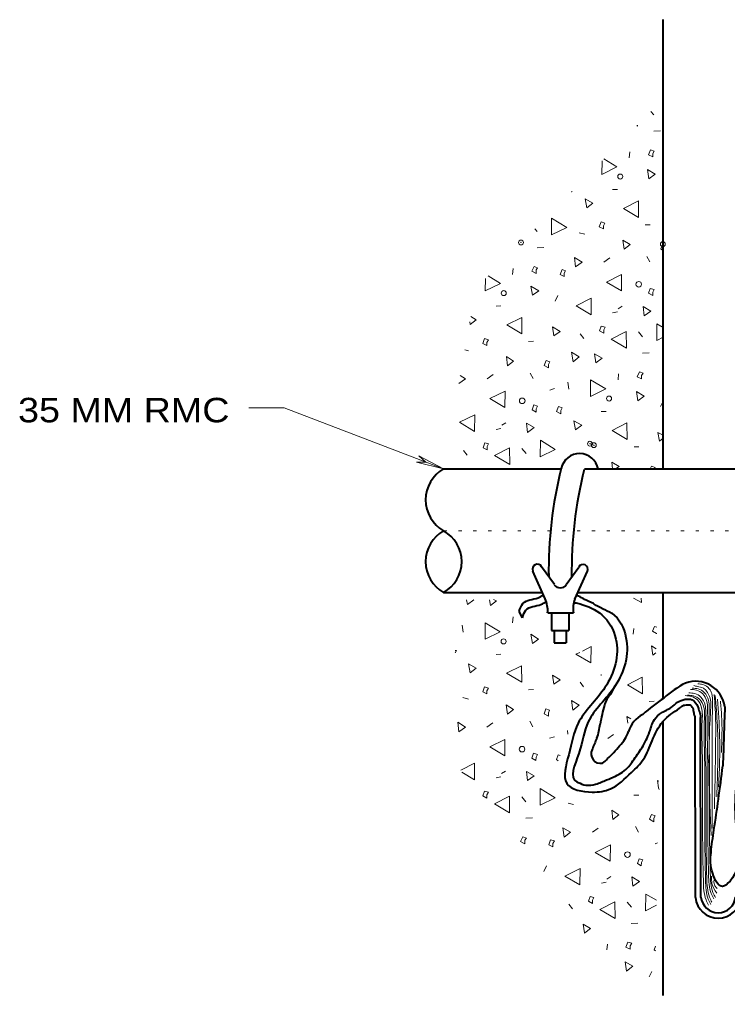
# Model space of a CAD drawing. Extents: x 312583 to 312854, y 144419 to 144597.
# Drawn here: x 312698.18 to 312720.15, y 144540.3 to 144570.57 of the extents above; entities that cross this region are included whole.
import ezdxf

# ---------------------------------------------------------------- set-up
doc = ezdxf.new("R2010")
doc.units = 0
doc.header["$LTSCALE"] = 0.3
doc.header["$PDMODE"] = 32
doc.header["$PDSIZE"] = 0.15
doc.linetypes.add('DOTTED', pattern=[1.5, 0.3, -1.2])
doc.layers.add('1', color=7, linetype='Continuous', lineweight=40)
doc.layers.add('2', color=7, linetype='Continuous', lineweight=13)

msp = doc.modelspace()

# ---------------------------------------------------------------- linework, layer by layer
at = {"layer": '1'}
for p, q in [((312718.1561, 144556.6347), (312718.1561, 144570.5727)), ((312711.3404, 144556.6347), (312714.9821, 144556.6347)), ((312715.7104, 144556.6347), (312731.4041, 144556.6347)), ((312714.4914, 144552.602), (312714.1081, 144553.4683)), ((312714.7751, 144553.0467), (312714.3764, 144553.5987)), ((312715.1431, 144553.0467), (312715.5341, 144553.591)), ((312715.4114, 144552.5943), (312715.8024, 144553.4607)), ((312711.3404, 144552.8013), (312714.3994, 144552.8013)), ((312713.5484, 144552.8013), (312714.3994, 144552.8013)), ((312715.5111, 144552.8013), (312720.4484, 144552.8013)), ((312718.1561, 144549.52), (312718.1561, 144552.8013)), ((312713.7861, 144552.0193), (312713.6864, 144552.211)), ((312714.5681, 144552.1727), (312715.3654, 144552.1727)), ((312714.6908, 144552.165), (312714.6908, 144551.6283)), ((312715.2198, 144552.165), (312715.2198, 144551.6283)), ((312714.6908, 144551.6283), (312715.2198, 144551.6283)), ((312714.7674, 144551.6283), (312714.7674, 144551.245)), ((312715.1431, 144551.6283), (312715.1431, 144551.245)), ((312714.7674, 144551.245), (312715.1431, 144551.245)), ((312716.5231, 144549.6503), (312716.6611, 144549.9033)), ((312718.1561, 144540.3047), (312718.1561, 144548.8147)), ((312719.1528, 144543.3407), (312719.1451, 144548.922)), ((312719.3214, 144543.3407), (312719.3138, 144548.922))]:
    msp.add_line(p, q, dxfattribs=at)
at = {"layer": '1', "linetype": 'DOTTED', "lineweight": 13}
msp.add_line((312711.3404, 144554.718), (312753.1391, 144554.718), dxfattribs=at)
at = {"layer": '1'}
for centre, radius, start, end in [((312715.5594, 144556.5275), 0.5827, 10.59906, 167.86288), ((312727.634, 144553.4784), 13.0359, 165.91883, 180.82259), ((312711.8803, 144555.6763), 1.0999, 119.39202, 240.60798), ((312728.347, 144553.4477), 13.0359, 165.91883, 180.72864), ((312711.8803, 144553.7597), 1.0999, 119.39202, 240.60798), ((312710.8006, 144553.7597), 1.0999, 299.39202, 60.60798), ((312714.2461, 144553.5297), 0.151, 27.89727, 203.96249), ((312715.6644, 144553.522), 0.151, 336.03751, 152.10273), ((312714.9591, 144553.1771), 0.23, 215.31121, 324.68879), ((312713.7248, 144552.257), 0.8438, 354.28941, 24.22774), ((312716.2011, 144552.2953), 0.8438, 159.26129, 188.35075), ((312720.4615, 144546.9445), 3.4521, 117.90046, 131.55753), ((312719.1582, 144549.1348), 0.9154, 7.82046, 109.93461), ((312717.1086, 144549.0993), 0.8041, 136.73863, 165.15216), ((312721.5728, 144544.4745), 6.0913, 123.94503, 131.71155), ((312723.9124, 144547.2022), 7.8673, 164.49454, 168.85639), ((313407.8138, 144525.3213), 688.1652, 178.00654, 178.15919), ((312717.9385, 144548.2183), 0.906, 117.53092, 162.36962), ((312714.6407, 144548.8469), 1.5576, 338.88002, 355.42457), ((312716.0631, 144548.8128), 1.0614, 313.90004, 342.44507), ((312724.9552, 144544.4191), 9.6682, 156.42656, 158.68794), ((312716.2077, 144547.7975), 0.2929, 152.43739, 282.29595), ((312714.524, 144549.8155), 2.881, 311.24609, 322.15663), ((312715.7948, 144548.1937), 0.8316, 304.86219, 319.11223), ((312719.8581, 144543.4097), 0.7073, 185.66371, 355.10091), ((312719.8581, 144543.4097), 0.5386, 185.66371, 355.10091)]:
    msp.add_arc(centre, radius, start, end, dxfattribs=at)
for points in [[(312713.6864, 144552.211), (312713.8014, 144552.464), (312714.2691, 144552.6403), (312714.4301, 144552.7247)], [(312716.2624, 144552.303), (312716.0938, 144552.3873), (312715.9864, 144552.4563), (312715.7104, 144552.5867), (312715.5264, 144552.6863), (312715.4651, 144552.7093)], [(312713.7861, 144552.0193), (312713.8934, 144552.257), (312714.3611, 144552.4333), (312714.5221, 144552.5177)], [(312715.4114, 144552.487), (312715.5724, 144552.4487), (312716.2471, 144552.1113), (312716.6841, 144551.36), (312716.3468, 144549.8573), (312715.5111, 144548.7457), (312715.2198, 144547.7643), (312715.1584, 144546.8827), (312715.9481, 144546.6143), (312716.5154, 144546.714), (312717.1671, 144547.22), (312717.5428, 144547.634), (312717.8111, 144548.2013), (312718.1484, 144548.807), (312718.6621, 144549.2133)], [(312716.2624, 144552.303), (312716.5614, 144552.1573), (312716.9984, 144551.406), (312716.6611, 144549.9033), (312715.8254, 144548.7917), (312715.5341, 144547.8103), (312715.4728, 144546.9287), (312715.5111, 144546.9133)], [(312715.5111, 144546.9133), (312715.7564, 144546.829), (312716.0554, 144546.8597), (312716.3928, 144546.99), (312716.6688, 144547.105), (312717.0828, 144547.404), (312717.2131, 144547.5803), (312717.4968, 144547.9943), (312717.7268, 144548.4773), (312717.8801, 144548.8607), (312718.0948, 144549.0677), (312718.4014, 144549.2363), (312718.6008, 144549.3973), (312718.8384, 144549.4893), (312719.0531, 144549.474), (312719.2294, 144549.2593), (312719.2601, 144549.1597), (312719.3061, 144548.991), (312719.3138, 144548.922)], [(312718.6621, 144549.2133), (312718.7618, 144549.29), (312718.8231, 144549.313), (312718.9228, 144549.3207), (312718.9764, 144549.3207), (312719.0301, 144549.2747), (312719.0684, 144549.221), (312719.0838, 144549.1367), (312719.1068, 144549.0447), (312719.1298, 144548.9603), (312719.1451, 144548.922)], [(312720.3948, 144546.668), (312720.3794, 144546.0777), (312720.3948, 144545.7097), (312720.2261, 144543.8543), (312719.9961, 144543.6857), (312719.6894, 144544.0843), (312719.6358, 144544.7437), (312719.7278, 144545.4413), (312719.8658, 144546.392), (312720.0038, 144547.427)]]:
    msp.add_spline(points, degree=3, dxfattribs=at)
at = {"layer": '1', "lineweight": 13}
for points in [[(312718.9458, 144549.6887), (312719.1298, 144549.6657), (312719.3214, 144549.5583), (312719.4518, 144549.313), (312719.4671, 144548.8837), (312719.4671, 144548.1477), (312719.4824, 144547.2353), (312719.4824, 144545.449), (312719.5054, 144543.9463), (312719.5898, 144543.356), (312719.6664, 144543.195)], [(312718.9994, 144549.796), (312719.1834, 144549.773), (312719.3751, 144549.6657), (312719.5054, 144549.4203), (312719.5208, 144548.991), (312719.5208, 144548.255), (312719.5361, 144547.3427), (312719.5361, 144545.5563), (312719.5591, 144544.0537), (312719.6434, 144543.4633), (312719.7201, 144543.3023)], [(312719.0531, 144549.8343), (312719.2371, 144549.8113), (312719.4288, 144549.704), (312719.5591, 144549.4587), (312719.5744, 144549.0293), (312719.5744, 144548.2933), (312719.5898, 144547.381), (312719.5898, 144545.5947), (312719.6128, 144544.092), (312719.6971, 144543.5017), (312719.7738, 144543.3407)], [(312719.1068, 144549.9187), (312719.2064, 144549.888), (312719.3981, 144549.8343), (312719.4978, 144549.7423), (312719.5898, 144549.5813), (312719.6204, 144549.0983), (312719.6434, 144545.265)], [(312719.6741, 144545.4873), (312719.6818, 144549.382), (312719.6588, 144549.6657), (312719.5821, 144549.819), (312719.3828, 144549.9493), (312719.2294, 144549.9723)], [(312718.8384, 144549.6043), (312719.0224, 144549.5813), (312719.2141, 144549.474), (312719.3444, 144549.2287), (312719.3598, 144548.7993), (312719.3598, 144548.0633), (312719.3751, 144547.151), (312719.3751, 144545.3647), (312719.3981, 144543.862), (312719.4824, 144543.2717), (312719.5591, 144543.1107)], [(312718.9074, 144549.6197), (312719.0914, 144549.5967), (312719.2831, 144549.4893), (312719.4134, 144549.244), (312719.4288, 144548.8147), (312719.4288, 144548.0787), (312719.4441, 144547.1663), (312719.4441, 144545.38), (312719.4671, 144543.8773), (312719.5514, 144543.287), (312719.6281, 144543.126)], [(312719.7354, 144549.635), (312719.7814, 144548.738), (312719.7814, 144548.3853), (312719.7431, 144546.093)], [(312719.7661, 144549.612), (312719.8351, 144548.669), (312719.8121, 144546.4687)], [(312719.8734, 144546.7677), (312719.9041, 144548.3623), (312719.8351, 144549.4893)], [(312719.9271, 144549.428), (312719.9654, 144548.991), (312719.9578, 144547.841)], [(312719.6511, 144544.0077), (312719.6664, 144543.7777), (312719.8121, 144543.4787)], [(312719.7201, 144543.8697), (312719.7584, 144543.701), (312719.8274, 144543.6243)]]:
    msp.add_spline(points, degree=3, dxfattribs=at)
at = {"layer": '2'}
for p, q in [((312717.7728, 144567.7207), (312717.8648, 144567.6133)), ((312717.3358, 144567.2837), (312717.3588, 144567.2683)), ((312717.3588, 144567.2683), (312717.3588, 144567.299)), ((312717.8571, 144567.1073), (312718.0641, 144567.1227)), ((312717.0981, 144566.287), (312717.1211, 144566.471)), ((312716.5844, 144565.3057), (312716.7301, 144565.3057)), ((312717.5964, 144564.2017), (312717.7498, 144564.2093)), ((312714.1694, 144564.079), (312714.2461, 144563.9947)), ((312715.5494, 144563.9563), (312715.7258, 144563.918)), ((312713.7324, 144563.6497), (312713.7401, 144563.6573)), ((312714.2384, 144563.4887), (312714.4531, 144563.504)), ((312716.4924, 144563.182), (312716.3084, 144563.0517)), ((312717.6424, 144563.228), (312717.7344, 144563.0593)), ((312713.4794, 144562.6683), (312713.5024, 144562.8523)), ((312714.8824, 144562.009), (312714.7981, 144561.8403)), ((312712.9658, 144561.687), (312713.1114, 144561.6947)), ((312716.5844, 144561.4723), (312716.7378, 144561.5107)), ((312716.7531, 144561.6027), (312716.8834, 144561.6793)), ((312712.1531, 144561.1963), (312712.1608, 144561.112)), ((312717.3894, 144560.882), (312717.5121, 144560.7287)), ((312718.1561, 144561.02), (312717.9568, 144561.135)), ((312713.9778, 144560.583), (312714.1311, 144560.5983)), ((312715.5801, 144560.8207), (312715.6874, 144560.675)), ((312711.9998, 144560.33), (312712.1071, 144560.2993)), ((312717.5121, 144560.2227), (312717.7191, 144560.238)), ((312712.8738, 144559.5633), (312712.6898, 144559.433)), ((312714.0238, 144559.6093), (312714.1158, 144559.4407)), ((312716.7531, 144559.4023), (312716.7684, 144559.5863)), ((312714.6371, 144559.0803), (312714.7751, 144559.1263)), ((312715.1891, 144559.3257), (312715.2198, 144559.111)), ((312718.1484, 144558.7353), (312718.0641, 144558.5667)), ((312716.2318, 144558.421), (312716.3851, 144558.421)), ((312712.9734, 144557.8537), (312713.1191, 144557.892)), ((312713.1421, 144557.9917), (312713.2724, 144558.0683)), ((312718.0334, 144557.4933), (312718.1561, 144557.5853)), ((312713.7708, 144557.271), (312713.9011, 144557.11)), ((312716.0018, 144557.3707), (312715.8791, 144557.4167)), ((312717.2514, 144557.317), (312717.3971, 144557.3247)), ((312710.5738, 144557.041), (312710.7884, 144556.8493)), ((312711.3404, 144556.6347), (312710.5738, 144557.041)), ((312711.9614, 144557.202), (312712.0688, 144557.064)), ((312710.4971, 144556.8417), (312710.7884, 144556.8493)), ((312711.3404, 144556.6347), (312710.4971, 144556.8417)), ((312712.0534, 144552.5713), (312712.0841, 144552.4257)), ((312712.7588, 144552.579), (312712.7894, 144552.395)), ((312717.2361, 144552.625), (312717.4814, 144552.4947)), ((312717.4814, 144552.4947), (312717.4738, 144552.625)), ((312713.4794, 144551.866), (312713.5024, 144552.05)), ((312711.9154, 144551.7893), (312711.9461, 144551.5747)), ((312717.2208, 144551.5057), (312717.2438, 144551.6897)), ((312712.9658, 144550.8847), (312713.1114, 144550.8923)), ((312717.8341, 144550.8617), (312717.9261, 144550.9307)), ((312715.5724, 144550.0183), (312715.6798, 144549.8727)), ((312716.2318, 144550.2637), (312716.2241, 144550.233)), ((312713.9778, 144549.7807), (312714.1311, 144549.796)), ((312711.9308, 144549.543), (312712.1071, 144549.497)), ((312717.7191, 144549.4203), (312717.8724, 144549.4357)), ((312714.0161, 144548.807), (312714.1081, 144548.6383)), ((312712.8661, 144548.761), (312712.6821, 144548.6307)), ((312715.1814, 144548.5233), (312715.1968, 144548.4083)), ((312714.6294, 144548.2857), (312714.7751, 144548.324)), ((312716.6151, 144548.4007), (312716.4311, 144548.278)), ((312713.1344, 144547.1893), (312713.2648, 144547.266)), ((312711.9078, 144547.2353), (312712.2988, 144546.9977)), ((312712.9658, 144547.0513), (312713.1114, 144547.0897)), ((312718.0181, 144546.9517), (312717.9798, 144546.967)), ((312713.7708, 144546.4687), (312713.8934, 144546.3077)), ((312717.2438, 144546.5147), (312717.3971, 144546.5223)), ((312715.2044, 144546.2693), (312715.3731, 144546.231)), ((312713.8858, 144545.8017), (312714.1004, 144545.817)), ((312716.1398, 144545.495), (312715.9558, 144545.3647)), ((312717.2898, 144545.541), (312717.3818, 144545.3723)), ((312717.9031, 144545.012), (312717.9798, 144545.035)), ((312714.5298, 144544.322), (312714.4454, 144544.1533)), ((312716.4081, 144543.9157), (312716.5308, 144543.9923)), ((312716.2394, 144543.7853), (312716.3851, 144543.8237)), ((312717.9414, 144543.2563), (312717.6118, 144543.448)), ((312715.2274, 144543.1337), (312715.3348, 144542.988)), ((312717.0368, 144543.195), (312717.1671, 144543.0417)), ((312717.1594, 144542.5357), (312717.3664, 144542.551)), ((312716.4004, 144541.7153), (312716.4234, 144541.8993)), ((312717.7958, 144541.0483), (312717.7191, 144540.8797))]:
    msp.add_line(p, q, dxfattribs=at)
for points in [[(312717.8264, 144566.4173), (312717.8724, 144566.494), (312717.7574, 144566.5323), (312717.6961, 144566.379), (312717.8264, 144566.31)], [(312717.7114, 144565.6353), (312717.9031, 144565.781), (312717.6654, 144565.919)], [(312715.7794, 144564.7307), (312715.9711, 144564.8763), (312715.7334, 144565.0143)], [(312717.3818, 144564.4317), (312717.3818, 144564.953), (312716.9218, 144564.7153)], [(312714.6908, 144564.4087), (312714.6831, 144563.895), (312715.1584, 144564.125)], [(312716.3008, 144564.171), (312716.3468, 144564.2553), (312716.2318, 144564.3013), (312716.1704, 144564.1403), (312716.3008, 144564.079)], [(312716.9371, 144563.4503), (312717.1288, 144563.596), (312716.8988, 144563.734)], [(312715.4344, 144562.906), (312715.6338, 144563.0517), (312715.3961, 144563.1897)], [(312714.2154, 144562.8063), (312714.2538, 144562.8753), (312714.1464, 144562.9137), (312714.0774, 144562.768), (312714.2154, 144562.6913)], [(312715.0818, 144562.7067), (312715.1201, 144562.7833), (312715.0128, 144562.8217), (312714.9591, 144562.6683), (312715.0818, 144562.5993)], [(312716.8604, 144562.1547), (312716.8604, 144562.6683), (312716.3928, 144562.4307)], [(312714.0928, 144562.0243), (312714.2921, 144562.1623), (312714.0468, 144562.308)], [(312717.8264, 144562.1163), (312717.8724, 144562.2007), (312717.7498, 144562.2313), (312717.6961, 144562.0857), (312717.8264, 144562.009)], [(312715.9174, 144561.4187), (312715.9174, 144561.9323), (312715.4498, 144561.6947)], [(312717.5658, 144561.3803), (312717.7651, 144561.526), (312717.5274, 144561.6717)], [(312713.7708, 144560.8207), (312713.7631, 144561.3343), (312713.3031, 144561.1043)], [(312714.7598, 144560.7593), (312714.9591, 144560.8973), (312714.7138, 144561.043)], [(312716.3084, 144560.951), (312716.3544, 144561.0277), (312716.2318, 144561.066), (312716.1781, 144560.9127), (312716.3084, 144560.8437)], [(312717.0138, 144560.3837), (312717.0061, 144560.8973), (312716.5384, 144560.6597)], [(312712.6821, 144560.56), (312712.7358, 144560.6367), (312712.6131, 144560.6827), (312712.5518, 144560.5293), (312712.6821, 144560.4603)], [(312713.3261, 144559.8317), (312713.5101, 144559.9773), (312713.2878, 144560.123)], [(312714.5911, 144559.8777), (312714.6371, 144559.9543), (312714.5221, 144559.9927), (312714.4608, 144559.8393), (312714.5911, 144559.7703)], [(312715.3578, 144559.9543), (312715.5494, 144560.1077), (312715.3118, 144560.2533)], [(312716.0631, 144559.9237), (312716.2548, 144560.0693), (312716.0171, 144560.2073)], [(312715.9021, 144559.4023), (312715.9021, 144558.881), (312716.3698, 144559.1187)], [(312717.4814, 144559.5327), (312717.5274, 144559.6093), (312717.4124, 144559.6477), (312717.3434, 144559.4943), (312717.4814, 144559.4253)], [(312713.2418, 144558.536), (312713.2494, 144559.0497), (312712.7741, 144558.8197)], [(312717.3664, 144558.7507), (312717.5581, 144558.8963), (312717.3204, 144559.0343)], [(312714.2154, 144558.4977), (312714.2538, 144558.582), (312714.1388, 144558.6203), (312714.0851, 144558.467), (312714.2078, 144558.398)], [(312714.9744, 144558.4517), (312715.0128, 144558.5283), (312714.9054, 144558.5667), (312714.8441, 144558.421), (312714.9744, 144558.3443)], [(312712.2988, 144557.8), (312712.3064, 144558.3137), (312711.8311, 144558.0837)], [(312713.9471, 144557.7693), (312714.1464, 144557.915), (312713.9088, 144558.053)], [(312715.4344, 144557.846), (312715.6261, 144557.9917), (312715.3808, 144558.1297)], [(312717.0368, 144557.547), (312717.0291, 144558.0683), (312716.5691, 144557.8307)], [(312712.6898, 144557.3323), (312712.7358, 144557.4167), (312712.6208, 144557.4473), (312712.5671, 144557.294), (312712.6898, 144557.225)], [(312713.3951, 144556.7727), (312713.3874, 144557.2863), (312712.9198, 144557.0487)], [(312714.3458, 144557.524), (312714.3381, 144557.0103), (312714.8058, 144557.2403)], [(312712.6284, 144551.866), (312712.6284, 144551.3523), (312713.0961, 144551.5823)], [(312714.0928, 144551.222), (312714.2844, 144551.36), (312714.0468, 144551.5057)], [(312712.1608, 144550.3097), (312712.3524, 144550.4553), (312712.1071, 144550.5933)], [(312713.7631, 144550.0183), (312713.7554, 144550.532), (312713.2954, 144550.302)], [(312714.7598, 144549.957), (312714.9514, 144550.095), (312714.7138, 144550.2407)], [(312717.5121, 144549.658), (312717.5044, 144550.1717), (312717.0444, 144549.9417)], [(312712.6821, 144549.7577), (312712.7281, 144549.8343), (312712.6131, 144549.8803), (312712.5518, 144549.727), (312712.6821, 144549.658)], [(312715.3501, 144549.152), (312715.5494, 144549.3053), (312715.3118, 144549.451)], [(312713.3184, 144549.0293), (312713.5101, 144549.175), (312713.2801, 144549.3207)], [(312714.5911, 144549.0753), (312714.6294, 144549.152), (312714.5144, 144549.1903), (312714.4608, 144549.0447), (312714.5911, 144548.968)], [(312711.8158, 144548.485), (312712.0151, 144548.6307), (312711.7774, 144548.7763)], [(312713.2418, 144547.7337), (312713.2418, 144548.2473), (312712.7741, 144548.0173)], [(312714.2078, 144547.6953), (312714.2538, 144547.7797), (312714.1311, 144547.818), (312714.0774, 144547.6647), (312714.2001, 144547.5957)], [(312713.9394, 144546.967), (312714.1464, 144547.1127), (312713.9088, 144547.2507)], [(312714.3381, 144546.7217), (312714.3304, 144546.208), (312714.8058, 144546.438)], [(312712.6821, 144546.53), (312712.7358, 144546.6143), (312712.6131, 144546.645), (312712.5594, 144546.4917), (312712.6821, 144546.4227)], [(312713.3874, 144545.9703), (312713.3874, 144546.484), (312712.9198, 144546.2463)], [(312716.5921, 144545.7633), (312716.7761, 144545.909), (312716.5538, 144546.047)], [(312717.8571, 144545.8017), (312717.9031, 144545.8783), (312717.7881, 144545.9167), (312717.7268, 144545.771), (312717.8571, 144545.6943)], [(312715.0818, 144545.219), (312715.2811, 144545.3647), (312715.0434, 144545.5027)], [(312713.8628, 144545.1193), (312713.9088, 144545.1883), (312713.7938, 144545.2267), (312713.7248, 144545.081), (312713.8628, 144545.0043)], [(312714.7291, 144545.0197), (312714.7751, 144545.0963), (312714.6601, 144545.1347), (312714.6064, 144544.9813), (312714.7291, 144544.9123)], [(312716.5078, 144544.4677), (312716.5154, 144544.9813), (312716.0401, 144544.7437)], [(312717.4814, 144544.4293), (312717.5198, 144544.5137), (312717.4048, 144544.5443), (312717.3511, 144544.3987), (312717.4738, 144544.322)], [(312715.5648, 144543.7317), (312715.5724, 144544.2453), (312715.0971, 144544.0077)], [(312717.2131, 144543.6933), (312717.4124, 144543.839), (312717.1748, 144543.9847)], [(312715.9558, 144543.264), (312716.0018, 144543.3407), (312715.8868, 144543.379), (312715.8331, 144543.2257), (312715.9558, 144543.1567)], [(312716.6611, 144542.6967), (312716.6534, 144543.2103), (312716.1858, 144542.9727)], [(312717.1288, 144541.8457), (312717.1748, 144541.9223), (312717.0598, 144541.9607), (312716.9984, 144541.8073), (312717.1288, 144541.7383)], [(312717.0138, 144541.0637), (312717.2054, 144541.2093), (312716.9678, 144541.3473)]]:
    msp.add_lwpolyline(points, close=True, dxfattribs=at)
for points in [[(312716.2548, 144566.1873), (312716.2471, 144565.7657), (312716.7148, 144566.0033), (312716.3084, 144566.2487)], [(312715.3118, 144565.229), (312715.3194, 144565.229), (312715.3194, 144565.2443)], [(312718.1408, 144563.6037), (312718.0794, 144563.458), (312718.1408, 144563.412)], [(312712.6438, 144562.5457), (312712.6284, 144562.1547), (312713.1038, 144562.3847), (312712.7204, 144562.6223)], [(312712.1608, 144561.112), (312712.3524, 144561.2577), (312712.1838, 144561.3573)], [(312717.9568, 144561.135), (312717.9568, 144560.6213), (312718.1484, 144560.721)], [(312711.8158, 144559.2873), (312712.0151, 144559.433), (312711.8541, 144559.5327)], [(312705.2991, 144558.5283), (312706.3954, 144558.5283), (312711.3404, 144556.6347)], [(312718.1561, 144557.6773), (312717.9874, 144557.7693), (312718.0334, 144557.4933)], [(312716.6764, 144556.6423), (312716.7838, 144556.7113), (312716.5538, 144556.8493), (312716.5844, 144556.6423)], [(312717.8724, 144556.6423), (312717.9031, 144556.6807), (312717.7881, 144556.719), (312717.7498, 144556.6423)], [(312712.0841, 144552.4257), (312712.2758, 144552.579), (312712.2681, 144552.579)], [(312712.7894, 144552.395), (312712.9811, 144552.5407), (312712.8891, 144552.5867)], [(312717.9568, 144551.728), (312717.8801, 144551.751), (312717.8188, 144551.6053)], [(312717.8188, 144551.6053), (312717.9491, 144551.5287), (312717.9568, 144551.5287)], [(312711.7008, 144550.9307), (312711.7391, 144550.9997), (312711.7008, 144550.9997)], [(312715.5648, 144550.946), (312715.4421, 144550.8923), (312715.9098, 144550.6163)], [(312715.9098, 144550.6163), (312715.9174, 144551.13), (312715.6491, 144550.9843)], [(312717.9338, 144551.0533), (312717.7881, 144551.1453), (312717.8341, 144550.8617)], [(312717.1518, 144548.8837), (312717.0291, 144548.9603), (312717.0521, 144548.7457)], [(312714.9514, 144547.749), (312714.8978, 144547.7643), (312714.8441, 144547.6187), (312714.8978, 144547.5803)], [(312712.2988, 144546.9977), (312712.2988, 144547.5113), (312711.8694, 144547.2967)], [(312717.9798, 144546.967), (312718.0104, 144546.7447), (312718.0258, 144546.691)], [(312717.6118, 144543.448), (312717.6041, 144542.9343), (312717.9414, 144543.1107)], [(312715.7104, 144542.2367), (312715.7181, 144542.2443), (312715.9021, 144542.3823), (312715.6644, 144542.5203)], [(312715.6644, 144542.5203), (312715.7104, 144542.252), (312715.7104, 144542.2367)], [(312717.9108, 144541.838), (312717.8724, 144541.7153), (312717.9108, 144541.6923)]]:
    msp.add_lwpolyline(points, dxfattribs=at)
for centre, radius in [((312716.8216, 144565.7032), 0.0783), ((312717.3942, 144562.3615), 0.0865), ((312713.2057, 144562.0873), 0.0783), ((312713.7783, 144558.7456), 0.0865), ((312716.4746, 144558.8183), 0.0783), ((312713.2014, 144551.2851), 0.0783), ((312713.774, 144547.9434), 0.0865), ((312717.043, 144544.6745), 0.0865)]:
    msp.add_circle(centre, radius, dxfattribs=at)
for p in [(312713.7401, 144563.6573), (312718.1408, 144563.6037), (312715.8791, 144557.4167), (312716.0018, 144557.3707)]:
    msp.add_point(p, dxfattribs=at)

# ---------------------------------------------------------------- texts
at = {"layer": '2', "width": 1.15}
msp.add_text('35 MM RMC', height=0.76, dxfattribs=at).set_placement((312698.1367, 144558.0796))

doc.saveas('drawing.dxf')
